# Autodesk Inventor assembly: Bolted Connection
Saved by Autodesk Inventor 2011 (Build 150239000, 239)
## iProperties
Created: 2020-12
Part Number: Bolted Connection
Document SubType Name: Assembly
Designer: PC
ClientObjectVersion: 1
Author: PC
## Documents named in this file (3)
- C:\Users\PC\Documents\Inventor\workshop-crane-powered-by-drill\estructura-principal\Design Accelerator\Bolted Connection4.iam
- C:\Users\PC\Documents\Inventor\Content Center Files\R2011\en-US\DIN 931-1\DIN 931-1 - M14 x 75.ipt
- C:\Users\PC\Documents\Inventor\Content Center Files\R2011\en-US\DIN 555\DIN 555-5 - M14.ipt
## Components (2 placed, 2 different names)
1. DIN 931-1 - replaced by DIN EN 24014 M14 x 75:1
2. DIN 555 - replaced by DIN EN 24034 M14:1
